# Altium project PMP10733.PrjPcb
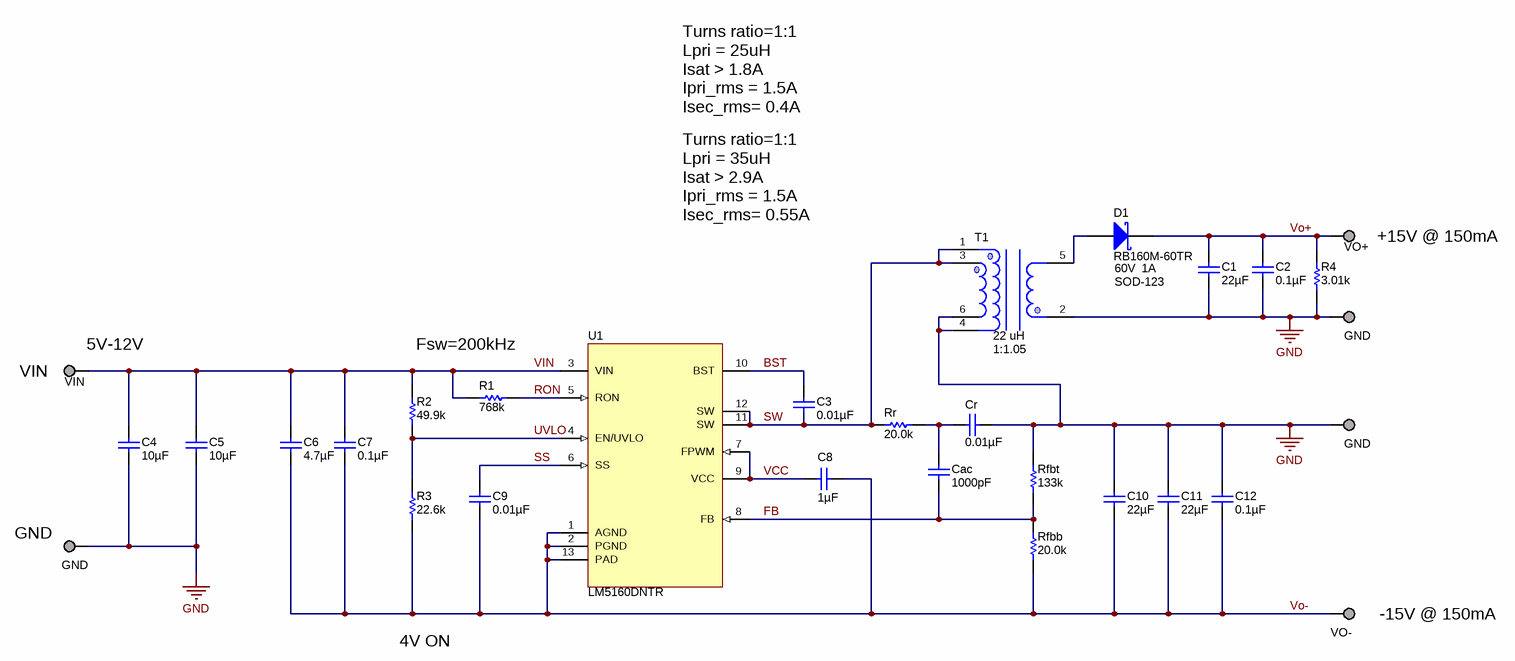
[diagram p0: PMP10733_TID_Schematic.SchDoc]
CopyrightYear: 2015; EVM_Orderable: N/A; PCB_Layout: N/A; PCB_Rev: E1; PRJ_Customer: Public Release; PRJ_Engineer: X Fang; PRJ_Number: PMP10733; PRJ_Title: +/-15V Non-isolated Fly-Buck; SCH_Rev: E3; TechSupport: http://www.ti.com/support; TID: PMP10733
2 sheets, 38 parts. Net scope: global (net labels, ports and power ports of the same name join across sheets).
Board file: PMP10733_TID.PcbDoc
Sheets:
  PMP10733_TID_Schematic.SchDoc
  PMP10733_TID_Hardware.SchDoc

## Sheet PMP10733_TID_Schematic.SchDoc
size 431 x 279 mm; Date: Not shown in title block; ApprovedBy: Not shown in title block; CheckedBy: Not shown in title block; Author: Not shown in title block; CompanyName: Not shown in title block; Engineer: Not shown in title block; Organization: Not shown in title block; Address1: Not shown in title block; Address2: Not shown in title block; Address3: Not shown in title block; Address4: Not shown in title block; DocumentNumber: 1; Revision: Use project parameter SCH_Rev; SheetNumber: 1; SheetTotal: 2; PageSetup: Record=PageOptions¦CenterHorizontal=True¦CenterVertical=True¦PrintScale=1.00¦XCorrection=1.00¦YCorrection=1.00¦PrintKind=0¦BorderSize=5000000¦LeftOffset=0¦BottomOffset=0¦Orientation=2¦PaperLength=1000¦PaperWidth=1000¦Scale=100¦PaperSource=15¦PrintQuality=600¦MediaType=1¦DitherType=10¦PaperKind=Letter¦PrintScaleMode=1

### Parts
C1  ValueDisplayed: 22µF  [1210L]  (hidden comment: GRM32ER71E226KE15L)
C2  ValueDisplayed: 0.1µF  [0603L]  (hidden comment: C1608X7R1H104K)
C3  ValueDisplayed: 0.01µF  [0603L]  (hidden comment: C1608X7R1H103K)
C4  ValueDisplayed: 10µF  [1206_190]  (hidden comment: C3216X7R1E106M160AE)
C5  ValueDisplayed: 10µF  [1206_190]  (hidden comment: C3216X7R1E106M160AE)
C6  ValueDisplayed: 4.7µF  [1206L]  (hidden comment: GRM31CR71H475KA12L)
C7  ValueDisplayed: 0.1µF  [0603L]  (hidden comment: C1608X7R1H104K)
C8  ValueDisplayed: 1µF  [0603L]  (hidden comment: C1608X7R1E105K080AB)
C9  ValueDisplayed: 0.01µF  [0603L]  (hidden comment: C1608X7R1H103K)
C10  ValueDisplayed: 22µF  [1210L]  (hidden comment: GRM32ER71E226KE15L)
C11  ValueDisplayed: 22µF  [1210L]
C12  ValueDisplayed: 0.1µF  [0603L]  (hidden comment: C1608X7R1H104K)
Cac  ValueDisplayed: 1000pF  [0603L]  (hidden comment: C1608X7R1H102K)
Cr  ValueDisplayed: 0.01µF  [0603L]  (hidden comment: GRM188R71H103KA01D)
D1  RB160M-60TR  value 60V  Value1: 1A  [SOD-123]
GND1  GND  [Keystone_5019]  (no BOM)
GND2  GND  [Keystone_5019]  (no BOM)
GND3  GND  [Keystone_5019]  (no BOM)
R1  ValueDisplayed: 768k  [0603L]  (hidden comment: CRCW0603768KFKEA)
R2  ValueDisplayed: 49.9k  [0603L]  (hidden comment: CRCW060349K9FKEA)
R3  ValueDisplayed: 22.6k  [0603L]  (hidden comment: CRCW060322K6FKEA)
R4  ValueDisplayed: 3.01k  [0603L]  (hidden comment: CRCW06033K01FKEA)
Rfbb  ValueDisplayed: 20.0k  [0603L]  (hidden comment: CRCW060320K0FKEA)
Rfbt  ValueDisplayed: 133k  [0603L]  (hidden comment: CRCW0603133KFKEA)
Rr  ValueDisplayed: 20.0k  [0603L]  (hidden comment: CRCW060320K0FKEA)
T1  value 22 uH  Turns Ratio: 1:1.05  [LPH8045-223]  (hidden comment: TA7848-AE)
U1  LM5160DNTR  [DNT0012B]
VIN  TESTPOINT  [Keystone_5019]  (value not drawn)  (no BOM)
VO+  TESTPOINT  [Keystone_5019]  (value not drawn)  (no BOM)
VO-  TESTPOINT  [Keystone_5019]  (value not drawn)  (no BOM)

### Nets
GND: C1.2 C2.2 C4.2 C5.2 C10.1 C11.1 C12.1 Cr.1 GND1.1 GND2.1 GND3.1 R4.1 Rfbt.2 T1.2 T1.4 T1.6
BST: C3.1 U1.10(BST)
FB: Cac.2 Rfbb.2 Rfbt.1 U1.8(FB)
RON: R1.2 U1.5(RON)
SS: C9.1 U1.6(SS)
SW: C3.2 Rr.1 T1.1 T1.3 U1.11(SW) U1.12(SW)
UVLO: R2.1 R3.2 U1.4(EN/UVLO)
VCC: C8.2 U1.7(FPWM) U1.9(VCC)
VIN: C4.1 C5.1 C6.1 C7.1 R1.1 R2.2 U1.3(VIN) VIN.1
Vo+: C1.1 C2.1 D1.1(K) R4.2 VO+.1
Vo-: C6.2 C7.2 C8.1 C9.2 C10.2 C11.2 C12.2 R3.1 Rfbb.1 U1.1(AGND) U1.2(PGND) U1.13(PAD) VO-.1
NetCac_1: Cac.1 Cr.2 Rr.2
NetD1_2: D1.2(A) T1.5

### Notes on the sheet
- Turns ratio=1:1
  Lpri = 25uH
  Isat > 1.8A
  Ipri_rms = 1.5A
  Isec_rms= 0.4A
- Turns ratio=1:1
  Lpri = 35uH
  Isat > 2.9A
  Ipri_rms = 1.5A
  Isec_rms= 0.55A
- (near VO+) +15V @ 150mA
- (near VIN) 5V-12V
- Fsw=200kHz
- (near VIN) VIN
- (near GND2) GND
- (near VO-) -15V @ 150mA
- 4V ON

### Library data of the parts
C1 C10 C11 = GRM32ER71E226KE15L: CAP, CERM, 22uF, 25V, +/-10%, X7R, 1210; Manufacturer: MuRata; Polarized: N; CompType: Capacitor; U/M: EA; Cap_F: 0.000022; Tolerance_%: 10; Value1: Unknown; VDC_V: 25; TaMin_C: -55; TaMax_C: 125; Cap_Case: 1210
C2 C7 C12 = C1608X7R1H104K: CAP, CERM, 0.1uF, 50V, +/-10%, X7R, 0603; Manufacturer: TDK; Polarized: N; CompType: Capacitor; U/M: EA; Cap_F: 0.0000001; Tolerance_%: 10; ESR_Ohm: 0.017; Value1: 0.017 ohm; VDC_V: 50; TaMin_C: -55; TaMax_C: 125; Cap_Case: 0603
C3 C9 = C1608X7R1H103K: CAP, CERM, 0.01uF, 50V, +/-10%, X7R, 0603; Manufacturer: TDK; Polarized: N; CompType: Capacitor; U/M: EA; Cap_F: 0.00000001; Tolerance_%: 10; ESR_Ohm: 0.0539; Value1: 0.0539 ohm; VDC_V: 50; TaMin_C: -55; TaMax_C: 125; Cap_Case: 0603
C4 C5 = C3216X7R1E106M160AE: CAP, CERM, 10 µF, 25 V, +/- 20%, X7R, 1206_190; Manufacturer: TDK; Polarized: N; CompType: Capacitor; Value: 10uF; U/M: EA; Cap_F: 0.00001; Tolerance_%: 20; Value1: Unknown; VDC_V: 25; Value2: 25V; TaMin_C: -55; TaMax_C: 125; Cap_Case: 1206
C6 = GRM31CR71H475KA12L: CAP, CERM, 4.7 µF, 50 V, +/- 10%, X7R, 1206; Manufacturer: MuRata; Polarized: N; CompType: Capacitor; Value: 4.7uF; U/M: EA; Cap_F: 0.0000047; Tolerance_%: 10; Value1: Unknown; VDC_V: 50; Value2: 50V; TaMin_C: -55; TaMax_C: 125; Cap_Case: 2220
C8 = C1608X7R1E105K080AB: CAP, CERM, 1uF, 25V, +/-10%, X7R, 0603; Manufacturer: TDK; Polarized: N; CompType: Capacitor; U/M: EA; Cap_F: 0.000001; Tolerance_%: 10; Value1: Unknown; VDC_V: 25; TaMin_C: -55; TaMax_C: 125; Cap_Case: 0603
Cac = C1608X7R1H102K: CAP, CERM, 1000pF, 50V, +/-10%, X7R, 0603; Manufacturer: TDK; Cap_Case: 0603; ESR_Ohm: 0.24; Polarized: N; TaMax_C: 125; TaMin_C: -55; Tolerance_%: 10; VDC_V: 50; Cap_F: 0.000000001; CompType: Capacitor; Value1: 0.24 ohm; U/M: EA
Cr = GRM188R71H103KA01D: CAP, CERM, 0.01uF, 50V, +/-10%, X7R, 0603; Manufacturer: MuRata; Polarized: N; CompType: Capacitor; U/M: EA; Cap_F: 0.00000001; Tolerance_%: 10; VDC_V: 50; TaMin_C: -55; TaMax_C: 125; Cap_Case: 0603
D1 = RB160M-60TR: Diode, Schottky, 60 V, 1 A, SOD-123; Manufacturer: Rohm; U/M: EA; Vf_V: 0.55; Value2: 0.55V; Io_A: 1; Vr_V: 60; TJmax_C: 150
GND1-GND3 VIN VO+ VO- = 5019: Test Point, Miniature, SMT; Manufacturer: Keystone; CompType: Test Point Loop; U/M: EA
R1 = CRCW0603768KFKEA: RES, 768 k, 1%, 0.1 W, 0603; Manufacturer: Vishay-Dale; CompType: Resistor; Value: 768k; Res_ohm: 768000; Tolerance_%: 1; Power_W: 0.1; Value2: 0.1W; VDC_V: 75; TempCo: 100 ppm/C; EIA_Code: E96; U/M: EA; AEC Category: Q200
R2 = CRCW060349K9FKEA: RES, 49.9 k, 1%, 0.1 W, 0603; Manufacturer: Vishay-Dale; CompType: Resistor; Tolerance_%: 1; VDC_V: 75; Power_W: 0.1; Res_ohm: 49900; Value: 49.9k; Value_Code: 49k9; Value2: 0.1W; EIA_Code: E96; TempCo: 100 ppm/C; U/M: EA; AEC Category: Q200
R3 = CRCW060322K6FKEA: RES, 22.6 k, 1%, 0.1 W, 0603; Manufacturer: Vishay-Dale; CompType: Resistor; Tolerance_%: 1; VDC_V: 75; Power_W: 0.1; Res_ohm: 22600; Value: 22.6k; Value_Code: 22k6; Value2: 0.1W; EIA_Code: E96; TempCo: 100 ppm/C; U/M: EA; AEC Category: Q200
R4 = CRCW06033K01FKEA: RES, 3.01 k, 1%, 0.1 W, 0603; Manufacturer: Vishay-Dale; CompType: Resistor; Tolerance_%: 1; VDC_V: 75; Power_W: 0.1; Res_ohm: 3010; Value: 3.01k; Value_Code: 3k01; Value2: 0.1W; EIA_Code: E96; TempCo: 100 ppm/C; U/M: EA; AEC Category: Q200
Rfbb = CRCW060320K0FKEA: RES, 20.0 k, 1%, 0.1 W, 0603; Manufacturer: Vishay-Dale; CompType: Resistor; Res_ohm: 20000; Value_Code: 20k0; Tolerance_%: 1; Power_W: 0.1; Value2: 0.1W; VDC_V: 75; TempCo: 100 ppm/C; EIA_Code: E96; U/M: EA; Value: 20.0k
Rfbt = CRCW0603133KFKEA: RES, 133 k, 1%, 0.1 W, 0603; Manufacturer: Vishay-Dale; CompType: Resistor; Res_ohm: 133000; Tolerance_%: 1; Power_W: 0.1; Value2: 0.1W; VDC_V: 75; TempCo: 100 ppm/C; EIA_Code: E96; U/M: EA; Value: 133k
Rr = CRCW060320K0FKEA: RES, 20.0 k, 1%, 0.1 W, 0603; Manufacturer: Vishay-Dale; CompType: Resistor; Tolerance_%: 1; VDC_V: 75; Power_W: 0.1; Res_ohm: 20000; Value: 20.0k; Value_Code: 20k0; Value2: 0.1W; EIA_Code: E96; TempCo: 100 ppm/C; U/M: EA
T1 = TA7848-AE: Coupled Inductor, 22uH, 1.35A Irms, 2A Isat, 1:1.05 turns ratio, LPH8045 Hexagonal Package; Manufacturer: Coilcraft
U1 = LM5160DNTR: Wide Input 65V, 1.5A Synchronous Step-Down DC-DC Converter, DNT0012B; Alternate PartNumber: LM5160DNTT; Manufacturer: Texas Instruments; SymbolCreator: a0411947; CompType: IC; U/M: EA

## Sheet PMP10733_TID_Hardware.SchDoc
size 431 x 279 mm; Date: Not shown in title block; ApprovedBy: Not shown in title block; CheckedBy: Not shown in title block; Author: Not shown in title block; CompanyName: Not shown in title block; Engineer: Not shown in title block; Organization: Not shown in title block; Address1: Not shown in title block; Address2: Not shown in title block; Address3: Not shown in title block; Address4: Not shown in title block; DocumentNumber: 2; Revision: Use project parameter SCH_Rev; SheetNumber: 2; SheetTotal: 2; PageSetup: Record=PageOptions¦CenterHorizontal=True¦CenterVertical=True¦PrintScale=1.00¦XCorrection=1.00¦YCorrection=1.00¦PrintKind=0¦BorderSize=5000000¦LeftOffset=0¦BottomOffset=0¦Orientation=2¦PaperLength=1000¦PaperWidth=1000¦Scale=100¦PaperSource=15¦PrintQuality=600¦MediaType=1¦DitherType=10¦PaperKind=Letter¦PrintScaleMode=1
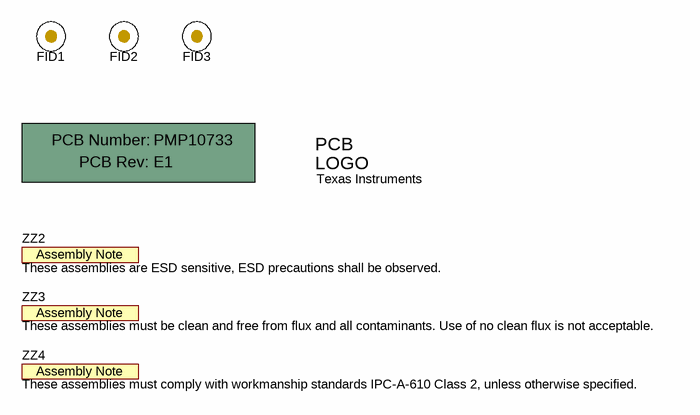
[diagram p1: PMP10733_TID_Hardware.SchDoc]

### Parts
!PCB  Printed Circuit Board  (value not drawn)  (mechanical)
FID1  Fiducial  [Fiducial10-20]  (value not drawn)
FID2  Fiducial  [Fiducial10-20]  (value not drawn)
FID3  Fiducial  [Fiducial10-20]  (value not drawn)
Logo1  Texas Instruments  [TI_Symbol_Overlay_Small]  (no BOM)
ZZ2  These assemblies are ESD sensitive, ESD precautions shall be observed.  [AssemblyNote]  (no BOM)
ZZ3  These assemblies must be clean and free from flux and all contaminants. Use of no clean flux is not acceptable.  [AssemblyNote]  (no BOM)
ZZ4  These assemblies must comply with workmanship standards IPC-A-610 Class 2, unless otherwise specified.  [AssemblyNote]  (no BOM)

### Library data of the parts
!PCB = PCB: Manufacturer: Any; PartNumber: PMP10733; SymbolCreator: a0412235
FID1-FID3 = Fiducial: Fiducial mark.  There is nothing to buy or mount.; SymbolCreator: codlsc
Logo1 = TI_Logo: Texas Instrument Corporate Signature; SymbolCreator: codlsc
ZZ2-ZZ4 = AssemblyNote: SymbolCreator: codlsc

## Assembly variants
001: not fitted FID1 FID2 FID3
